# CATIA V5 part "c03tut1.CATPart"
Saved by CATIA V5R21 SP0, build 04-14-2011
Part number: Part1
Bounding box of the stored display mesh (mm): x 0 to 0, y -100 to 100, z -118.146 to 124.124
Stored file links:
  D:\CATIA V5R21 E-RESOURCES\CATIA-V5R21\catia-v5r21-prt\c03-catia-v5r21-prt\catia-v5r21-tut-01.CATPart
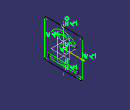
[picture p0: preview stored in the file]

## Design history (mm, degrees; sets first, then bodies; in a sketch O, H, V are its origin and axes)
Body1 (main body)
  Sketch1 on yz-plane, origin (0, 0, 0), H (0, 1, 0), V (0, 0, 1)
    line L1 (100, 90) -> (100, -90)
    line L2 (90, -100) -> (-90, -100)
    line L3 (-100, -90) -> (-100, 90)
    line L4 (-90, 100) -> (90, 100)
    construction line L5 (-70, -70) -> (70, -70)
    line L6 (-70, -60) -> (70, -60)
    line L7 (70, -80) -> (-70, -80)
    arc A1 centre (70, -70) radius 10 from (70, -60) to (70, -80) cw
    arc A2 centre (-70, -70) radius 10 from (-70, -80) to (-70, -60) cw
    point P3 (-70, -60)
    point P4 (70, -60)
    construction arc A3 centre (0, 0) radius 70 from (57.4456, 40) to (-57.4456, 40) ccw
    arc A4 centre (57.4456, 40) radius 10 from (65.6521, 45.7143) to (49.2391, 34.2857) cw
    arc A5 centre (-57.4456, 40) radius 10 from (-49.2391, 34.2857) to (-65.6521, 45.7143) cw
    arc A6 centre (0, 0) radius 60 from (49.2391, 34.2857) to (-49.2391, 34.2857) ccw
    arc A7 centre (0, 0) radius 80 from (-65.6521, 45.7143) to (65.6521, 45.7143) cw
    circle A8 centre (0, 0) radius 20
    arc A9 centre (90, 90) radius 10 from (100, 90) to (90, 100) ccw
    arc A10 centre (-90, 90) radius 10 from (-100, 90) to (-90, 100) cw
    arc A11 centre (-90, -90) radius 10 from (-90, -100) to (-100, -90) cw
    arc A12 centre (90, -90) radius 10 from (100, -90) to (90, -100) cw
    reference intersected line E1 through (0, 0) direction (-1, 0) from xy-plane
    reference intersected line E3 through (0, 0) direction (0, 1) from zx-plane
    axis line L8 (0, 124.1239) -> (0, -118.1456)
    point P25 (0, 124.1239)
    radius A5 = 10
    radius A9 = 10
    radius A10 = 10
    radius A12 = 10
    radius A7 = 80
    radius A8 = 20
    distance V L1 = 100
    distance P3 P4 = 140
    distance L6 L7 = 20
    radius A11 = 10
    vertical: L1 V, L3 V, E3 V, L8 V
    horizontal: L2 H, L4 H, L5 H, E1 H
    equidistance: L1 L3 O, L2 L4 O
    tangency: A1 L6, A2 L6, A1 L7, A2 L7, A3 L5, A6 A5, A5 A7, A7 A4, A4 A6, A9 L1, A9 L4, A10 L3, A10 L4, A11 L2, A11 L3, A12 L1, A12 L2
    parallelism: L5 L6, L7 L2
    concentricity: A6 O, A7 O
    coincidence: P25 V
    fix: A8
